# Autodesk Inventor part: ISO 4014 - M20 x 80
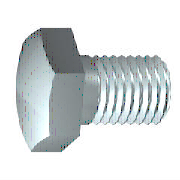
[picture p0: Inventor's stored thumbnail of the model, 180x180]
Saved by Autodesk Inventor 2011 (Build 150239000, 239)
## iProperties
IsCustomPart: 0
Created: 2009-02
Part Number: ISO 4014 - M20 x 80
Material: Stainless Steel, 440C
Description: Hexagon head bolt - product grades A and B
Document SubType Name: Modeling
Standard: ISO 4014
Designer: V.de Jong
Standard Revision: Third edition 1999-09-01
Standards Organization: ISO
Language: en-US
Size Designation: M20 x 80
Categories: <MemberInstance><Categories><Category DisplayName="Fasteners" InternalName="e4da775c-781d-43d5-af7c-5136215cf5a6" Mnemonic="FSTN"><Category DisplayName="Bolts"
Density: 7.75 g/cm^3
Mass: 268.552 g
Surface Area: 77.7611 cm^2
Volume: 34.6519 cm^3
Author: V.de Jong
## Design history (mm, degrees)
workplane "Work Plane1"
revolve "Body" stored, may be unused: angle "d12" = 90 deg
sketch "Sketch2"
  geometry: L1 (0, 17.321)-(15, 8.66); L2 (15, 8.66)-(15, -8.66); L3 (15, -8.66)-(0, -17.321); L4 (0, -17.321)-(-15, -8.66); L5 (-15, -8.66)-(-15, 8.66); L6 (-15, 8.66)-(0, 17.321); 2 further points
  constraints: 12 end point, 1 coincident, 1 vertical, 11 other
  dimensions: "d11" = 30 distance between parallel lines of L5 L2 (= SW)
extrude "Head" join sketch "Sketch2" distance "d3" = 11.7 (= KOH - SD); taper "d4" = 0 deg
revolve "Chamfer1" stored, may be unused: angle "d21" = 90 deg
body "Solid1"
feature "Thread" dims "d15" = 46 (= GEL), "d16" = 0
chamfer "Chamfer2" distance "d6" = 1.53363 (= -0.5 x SPD + 0.5 x GD); stored, may be unused: second distance "d7" = 1.53373 (computed from GUL), angle "d55" = 45 deg
sketch "Sketch1"
  geometry: L1 (0, 14.095)-(0, 10); L2 (34, 10)-(80, 10); L3 (80, 10)-(80, 0); L4 (80, 0)-(-0.8, 0); L5 (-16.96, 0)-(96.16, 0) reference; L6 (-0.8, 0)-(-0.8, 14.095); L7 (-0.8, 14.095)-(0, 14.095); L8 (34, 10)-(32.466, 10); L9 (32.466, 10)-(0, 10); L10 (0, -2.819)-(0, 16.914) reference
  constraints: 16 end point, 2 collinear, 2 perpendicular, 1 parallel
  dimensions: "d0" = 80 distance between parallel lines of L3 L1 (= NLG); "d1" = 46 distance from line of L2.start L3 (= GEL); "d2" = 20 diameter of L2 L4 (= GD); "d9" = 0.8001 distance between parallel lines of L6 L1 (computed from SD); "d10" = 28.19 diameter of L7 L4 (= SD2); "d13" = 1.53373 distance of L2.start L8.end (computed from GAL); "d14" = 20 diameter of L9 L4 (= BDM)
sketch "Sketch4"
  geometry: L1 (-12.5, 15)-(-12.5, 17.321); L2 (-12.5, 17.321)-(-11.16, 17.321); L3 (-11.16, 17.321)-(-12.5, 15); L4 (-14.84, 0)-(1.54, 0) reference; L5 (-0.8, 17.321)-(-12.5, 17.321) reference; L6 (-12.5, 8.66)-(-12.5, 17.321) reference
  constraints: 6 end point, 2 collinear, 1 perpendicular, 1 vertical
  dimensions: "d5" = 30 deg angle of L3 L1 (= ANG1); "d19" = 30 diameter of L1.start L4 (= SW0)
other parameters: "NLG" = 80 [user parameter; used in 1 equation term], "GD" = 20 (= NND) [user parameter; used in 2 equation terms], "BDM" = 20 (= NND) [user parameter; used in 1 equation term], "KOH" = 12.5 [user parameter; used in 1 equation term], "GEL" = 46 [user parameter; used in 2 equation terms], "SW" = 30 [user parameter; used in 3 equation terms], "SW0" = 30 (= SW) [user parameter; used in 1 equation term], "SPD" = 16.93275 (= NND - 1.2269 x PTC) [user parameter; used in 1 equation term], "SD2" = 28.19 [user parameter; used in 2 equation terms], "SD" = 0.8 [user parameter; used in 2 equation terms], "ANG1" = 30 deg [user parameter; used in 1 equation term], "GAL" = 1.53363 (= 0.61345 x PTC) [user parameter; used in 1 equation term], "GUL" = 1.53363 (= 0.61345 x PTC) [user parameter; used in 1 equation term], "d8" = 0, "RR" = 0.8 [user parameter], "d57" = 0, "d58" = 0, "TPU" = 4 (computed from PTC) [user parameter], "GD1" = 16.93275 (= THREADDIA - 1.2269 x PTC) [user parameter], "SDH" = 28.19 (= SD2) [user parameter], "TOA" = 30 deg [user parameter], "PTC" = 2.5 [user parameter; used in 5 equation terms], "E0" = 34.65 (= 1.155 x SW) [user parameter]
